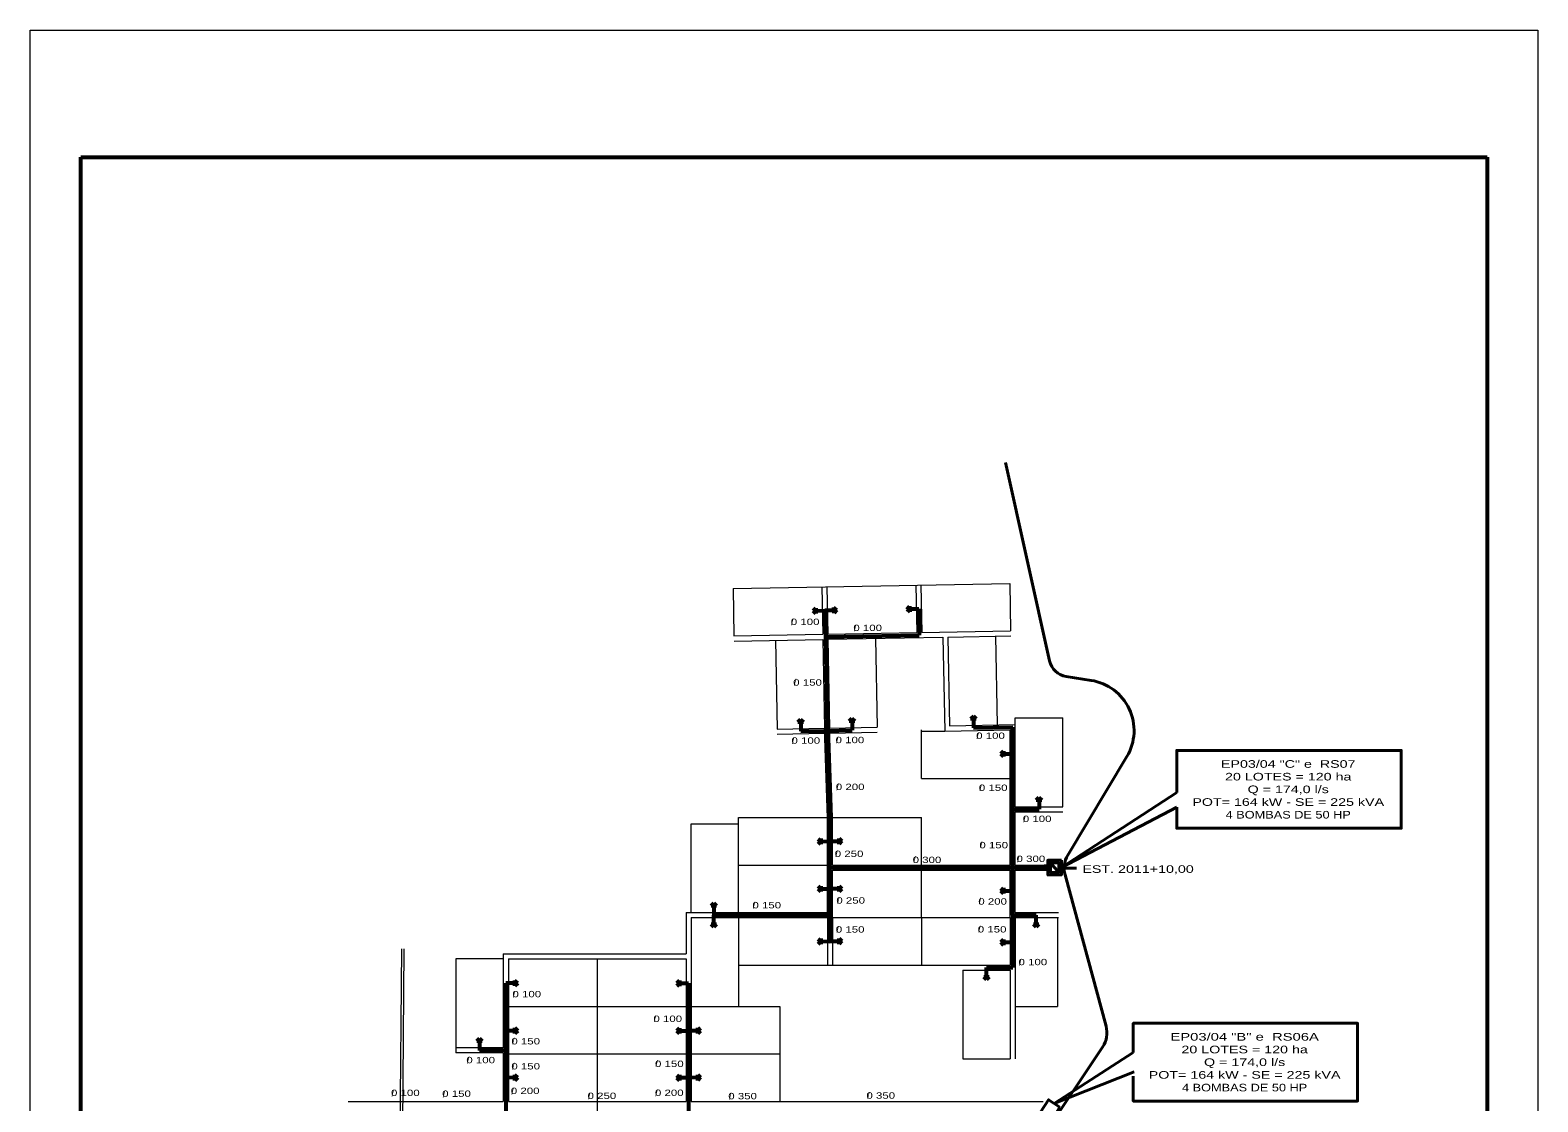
# Model space of a CAD drawing. Extents: x 312964 to 351929, y 9004151 to 9034973.
# Drawn here: x 326200 to 332140, y 9017535 to 9021758 of the extents above; entities that cross this region are included whole.
import ezdxf
from ezdxf.enums import TextEntityAlignment as Align

# ---------------------------------------------------------------- set-up
doc = ezdxf.new("R2010")
doc.units = 0
doc.header["$LTSCALE"] = 10
for name, color, linetype, lineweight in [('1', 7, 'Continuous', 13), ('2', 7, 'Continuous', 53), ('6', 7, 'Continuous', 13)]:
    doc.layers.add(name, color=color, linetype=linetype, lineweight=lineweight)

msp = doc.modelspace()

# ---------------------------------------------------------------- linework, layer by layer
at = {"layer": '1'}
for p, q in [((326200.21, 9017557.86), (326200.21, 9021757.86)), ((328969.59, 9019557.81), (328973.09, 9019370.84)), ((329319.53, 9019564.35), (329323.03, 9019377.38)), ((329339.53, 9019564.73), (329343.02, 9019377.76)), ((329689.47, 9019571.27), (329692.96, 9019384.3)), ((329709.46, 9019571.64), (329712.96, 9019384.67)), ((328973.09, 9019370.84), (329323.03, 9019377.38)), ((328973.46, 9019350.85), (329323.4, 9019357.39)), ((329323.4, 9019357.39), (329329.94, 9019007.31)), ((329343.02, 9019377.76), (329692.96, 9019384.3)), ((329343.4, 9019357.76), (329796.32, 9019366.23)), ((329343.4, 9019357.76), (329349.94, 9019007.82)), ((329530.36, 9019361.26), (329536.9, 9019011.32)), ((329712.96, 9019384.67), (330062.9, 9019391.21)), ((329816.31, 9019366.6), (330063.27, 9019371.22)), ((329816.31, 9019366.6), (329822.85, 9019016.66)), ((330003.28, 9019370.1), (330009.82, 9019020.16)), ((329136.43, 9019353.89), (329142.97, 9019003.95)), ((329142.97, 9019003.95), (329329.94, 9019007.45)), ((329341.4, 9018654.85), (329329.94, 9019007.31)), ((329349.94, 9019007.82), (329536.9, 9019011.32)), ((329361.4, 9018655.18), (329349.94, 9019007.82)), ((329711.4, 9018809.29), (329711.4, 9019001.12)), ((329822.85, 9019016.66), (330081.4, 9019021.49)), ((330061.4, 9018468.18), (330061.4, 9019001.12)), ((330081.4, 9019048.18), (330268.4, 9019048.18)), ((330081.4, 9018698.18), (330081.4, 9019048.18)), ((330268.4, 9018698.18), (330268.4, 9019048.18)), ((329143.35, 9018983.96), (329330.31, 9018987.45)), ((329350.31, 9018987.83), (329537.28, 9018991.32)), ((329711.4, 9018996.29), (329803.23, 9018996.29)), ((329711.4, 9018809.29), (330061.4, 9018809.29)), ((328991.4, 9018281.18), (328991.4, 9018655.18)), ((328991.4, 9018655.18), (329341.4, 9018655.18)), ((329341.4, 9018281.18), (329341.4, 9018654.85)), ((329361.4, 9018655.18), (329711.4, 9018655.18)), ((329361.4, 9018468.18), (329361.4, 9018655.18)), ((329711.4, 9018468.18), (329711.4, 9018655.18)), ((330081.4, 9018698.18), (330268.4, 9018698.18)), ((330081.4, 9018678.18), (330268.4, 9018678.18)), ((330081.4, 9018468.18), (330081.4, 9018678.18)), ((328804.4, 9018281.18), (328804.4, 9018631.18)), ((328804.4, 9018631.18), (328991.4, 9018631.18)), ((328991.4, 9018468.18), (329341.4, 9018468.18)), ((329361.4, 9018468.18), (330061.4, 9018468.18)), ((330081.4, 9018468.18), (330194.61, 9018468.18)), ((329361.4, 9018448.18), (330061.4, 9018448.18)), ((329361.4, 9018261.18), (329361.4, 9018448.18)), ((329711.4, 9018261.18), (329711.4, 9018448.18)), ((330061.4, 9018261.18), (330061.4, 9018448.18)), ((330081.4, 9018448.18), (330194.66, 9018448.18)), ((330081.4, 9018281.18), (330081.4, 9018448.18)), ((328784.4, 9018281.18), (328784.4, 9018118.18)), ((328784.4, 9018281.18), (329341.4, 9018281.18)), ((328804.4, 9018261.18), (329341.4, 9018261.18)), ((328804.4, 9018261.18), (328804.4, 9017537.18)), ((328991.4, 9018261.18), (328991.4, 9017911.18)), ((329341.4, 9018261.18), (329341.4, 9018074.18)), ((329361.4, 9018261.18), (329361.4, 9018074.18)), ((329361.4, 9018261.18), (330061.4, 9018261.18)), ((329711.4, 9018261.18), (329711.4, 9018074.18)), ((330061.4, 9018261.18), (330061.4, 9018074.18)), ((330081.4, 9018281.18), (330251.39, 9018281.18)), ((330081.4, 9018261.18), (330081.4, 9017704.18)), ((330081.4, 9018261.18), (330251.44, 9018261.18)), ((330248.4, 9018261.18), (330248.4, 9017911.18)), ((328064.4, 9018118.18), (328784.4, 9018118.18)), ((328064.4, 9018118.18), (328064.4, 9017748.18)), ((327877.4, 9018098.18), (327877.4, 9017728.18)), ((328064.4, 9018098.18), (327877.4, 9018098.18)), ((328084.4, 9018098.18), (328784.4, 9018098.18)), ((328084.4, 9018098.18), (328084.4, 9017537.18)), ((328434.4, 9018098.18), (328434.4, 9016208.18)), ((328784.4, 9018098.18), (328784.4, 9017537.18)), ((328991.4, 9018074.18), (330061.4, 9018074.18)), ((329874.4, 9018054.18), (330061.4, 9018054.18)), ((329874.4, 9018054.18), (329874.4, 9017704.18)), ((330061.4, 9018054.18), (330061.4, 9017704.18)), ((328084.4, 9017911.18), (329154.4, 9017911.18)), ((328804.4, 9017911.18), (329154.4, 9017911.18)), ((329154.4, 9017911.18), (329154.4, 9017537.18)), ((330081.4, 9017911.18), (330248.4, 9017911.18)), ((328064.4, 9017748.18), (327877.4, 9017748.18)), ((328064.4, 9017728.18), (327877.4, 9017728.18)), ((328064.4, 9017728.18), (328064.4, 9017537.18)), ((328084.4, 9017724.18), (328784.4, 9017724.18)), ((328804.4, 9017724.18), (329154.4, 9017724.18)), ((329874.4, 9017704.18), (330061.4, 9017704.18)), ((327453.4, 9017537.18), (328064.4, 9017537.18)), ((328084.4, 9017537.18), (328784.4, 9017537.18))]:
    msp.add_line(p, q, dxfattribs=at)
at = {"layer": '1', "lineweight": 53}
for p, q in [((326400.21, 9013557.86), (326400.21, 9021257.86)), ((326400.21, 9021257.86), (331940.21, 9021257.86)), ((331940.21, 9021257.86), (331940.21, 9013557.86))]:
    msp.add_line(p, q, dxfattribs=at)
at = {"layer": '1', "lineweight": 40}
for p, q in [((330216.08, 9019272.99), (330042.9, 9020054.18)), ((330380.24, 9019195.92), (330281.85, 9019211.26)), ((330288.23, 9018506.66), (330521.02, 9018895.59)), ((330209.65, 9018450.72), (330194.61, 9018465.68)), ((330209.61, 9018465.72), (330194.65, 9018450.68)), ((330219.58, 9018477.4), (330253.07, 9018439.16)), ((330439.01, 9017833.07), (330277.52, 9018429.15)), ((330190.37, 9017399.2), (330425.64, 9017751.37))]:
    msp.add_line(p, q, dxfattribs=at)
at = {"layer": '1'}
for points in [[(326200.21, 9021757.86), (332140.21, 9021757.86), (332140.21, 9017557.86)], [(328969.59, 9019557.81), (330059.4, 9019578.18), (330062.9, 9019391.21)], [(329796.32, 9019366.23), (329803.23, 9018996.29), (330061.4, 9019001.12)], [(332140.21, 9017557.86), (332140.21, 9013357.86), (326200.21, 9013357.86), (326200.21, 9017557.86)], [(328804.4, 9017537.18), (329154.4, 9017537.18), (330190.66, 9017537.18)]]:
    msp.add_lwpolyline(points, dxfattribs=at)
at = {"layer": '1', "lineweight": 40}
for points in [[(330194.61, 9018465.68), (330194.65, 9018450.68), (330209.65, 9018450.72), (330209.61, 9018465.72)], [(330262.95, 9018487.51), (330263.09, 9018429.19), (330209.7, 9018429.06), (330209.56, 9018487.38)], [(330252.97, 9018477.49), (330253.07, 9018439.16), (330219.68, 9018439.08), (330219.58, 9018477.4)], [(330219.58, 9018477.4), (330252.97, 9018477.49), (330253.07, 9018439.16)], [(330257.28, 9017514.07), (330225.3, 9017465.29), (330180.65, 9017494.57), (330212.63, 9017543.34)]]:
    msp.add_lwpolyline(points, close=True, dxfattribs=at)
for centre, radius, start, end in [((330294.19, 9019290.31), 80, 192.49974, 261.1331), ((330349.41, 9018998.31), 200, 329.09823, 81.13306), ((330374.04, 9018455.3), 100, 149.09824, 195.159), ((330342.49, 9017806.92), 100, 326.25468, 15.15895)]:
    msp.add_arc(centre, radius, start, end, dxfattribs=at)
at = {"layer": '2'}
for p, q in [((329284.66, 9019469.93), (329295.24, 9019480.91)), ((329295.24, 9019480.91), (329295.64, 9019459.35)), ((329367.31, 9019461.2), (329366.91, 9019482.76)), ((329377.89, 9019472.18), (329366.91, 9019482.76)), ((329654.6, 9019476.84), (329665.17, 9019487.82)), ((329654.6, 9019476.84), (329665.57, 9019466.27)), ((329665.17, 9019487.82), (329665.57, 9019466.27)), ((329665.37, 9019477.3), (329701.21, 9019477.97)), ((329701.21, 9019477.97), (329703.15, 9019374.49)), ((329284.66, 9019469.93), (329295.64, 9019459.35)), ((329295.43, 9019470.39), (329331.28, 9019471.05)), ((329367.12, 9019471.72), (329331.28, 9019471.05)), ((329331.28, 9019471.06), (329333.21, 9019367.57)), ((329377.89, 9019472.18), (329367.31, 9019461.2)), ((329333.21, 9019367.57), (329703.15, 9019374.49)), ((329333.21, 9019367.57), (329339.94, 9019007.64)), ((329235.65, 9019042.32), (329225.08, 9019031.34)), ((329246.63, 9019031.74), (329225.08, 9019031.34)), ((329235.65, 9019042.32), (329246.63, 9019031.74)), ((329236.11, 9019031.55), (329236.78, 9018995.71)), ((329335.33, 9018997.55), (329438.81, 9018999.48)), ((329351.41, 9018654.86), (329339.94, 9019007.5)), ((329437.69, 9019046.1), (329427.11, 9019035.12)), ((329448.66, 9019035.52), (329427.11, 9019035.12)), ((329437.69, 9019046.1), (329448.66, 9019035.52)), ((329438.15, 9019035.32), (329438.81, 9018999.48)), ((329916.42, 9019055.04), (329905.61, 9019044.3)), ((329927.17, 9019044.22), (329905.61, 9019044.3)), ((329916.42, 9019055.04), (329927.17, 9019044.22)), ((329916.64, 9019044.26), (329916.52, 9019008.41)), ((329916.52, 9019008.41), (330071.4, 9019011.31)), ((330071.4, 9018271.18), (330071.4, 9019011.31)), ((329236.78, 9018995.71), (329340.26, 9018997.64)), ((330024.77, 9018906.39), (330035.59, 9018917.14)), ((330024.77, 9018906.39), (330035.52, 9018895.58)), ((330035.59, 9018917.14), (330035.52, 9018895.58)), ((330035.55, 9018906.62), (330071.4, 9018906.5)), ((330174.8, 9018734.81), (330163.98, 9018724.07)), ((330185.54, 9018723.99), (330163.98, 9018724.07)), ((330174.8, 9018734.81), (330185.54, 9018723.99)), ((330175.02, 9018724.03), (330174.9, 9018688.18)), ((330071.4, 9018688.18), (330174.9, 9018688.18)), ((329304.77, 9018561.58), (329315.59, 9018572.32)), ((329304.77, 9018561.58), (329315.52, 9018550.76)), ((329315.59, 9018572.32), (329315.52, 9018550.76)), ((329315.55, 9018561.8), (329351.4, 9018561.68)), ((329387.25, 9018561.56), (329351.4, 9018561.68)), ((329387.21, 9018551.04), (329387.29, 9018572.6)), ((329398.03, 9018561.78), (329387.21, 9018551.04)), ((329398.03, 9018561.78), (329387.29, 9018572.6)), ((329351.4, 9018458.18), (330194.63, 9018458.18)), ((329304.77, 9018374.58), (329315.59, 9018385.32)), ((329304.77, 9018374.58), (329315.52, 9018363.76)), ((329315.59, 9018385.32), (329315.52, 9018363.76)), ((329315.55, 9018374.8), (329351.4, 9018374.68)), ((329387.25, 9018374.56), (329351.4, 9018374.68)), ((329387.21, 9018364.04), (329387.29, 9018385.6)), ((329398.03, 9018374.78), (329387.21, 9018364.04)), ((329398.03, 9018374.78), (329387.29, 9018385.6)), ((330024.77, 9018367.16), (330035.59, 9018377.9)), ((330024.77, 9018367.16), (330035.52, 9018356.35)), ((330035.59, 9018377.9), (330035.52, 9018356.35)), ((330035.55, 9018367.38), (330071.4, 9018367.26)), ((328893.88, 9018317.81), (328883.06, 9018307.07)), ((328904.62, 9018306.99), (328883.06, 9018307.07)), ((328893.88, 9018317.81), (328904.62, 9018306.99)), ((328894.1, 9018307.03), (328893.98, 9018271.18)), ((328883.34, 9018235.37), (328904.9, 9018235.3)), ((328894.08, 9018224.55), (328883.34, 9018235.37)), ((328893.86, 9018235.33), (328893.98, 9018271.18)), ((328894.08, 9018224.55), (328904.9, 9018235.3)), ((329351.4, 9018271.18), (329351.4, 9018167.68)), ((330071.4, 9018271.18), (330071.4, 9018064.18)), ((330071.4, 9018271.18), (330163.57, 9018271.18)), ((330152.93, 9018235.37), (330174.49, 9018235.3)), ((330163.68, 9018224.55), (330152.93, 9018235.37)), ((330163.45, 9018235.33), (330163.57, 9018271.18)), ((330163.68, 9018224.55), (330174.49, 9018235.3)), ((329304.77, 9018167.58), (329315.59, 9018178.32)), ((329304.77, 9018167.58), (329315.52, 9018156.76)), ((329315.59, 9018178.32), (329315.52, 9018156.76)), ((329315.55, 9018167.8), (329351.4, 9018167.68)), ((329387.25, 9018167.56), (329351.4, 9018167.68)), ((329387.21, 9018157.04), (329387.29, 9018178.6)), ((329398.03, 9018167.78), (329387.21, 9018157.04)), ((329398.03, 9018167.78), (329387.29, 9018178.6)), ((330024.77, 9018164.03), (330035.59, 9018174.77)), ((330035.59, 9018174.77), (330035.52, 9018153.21)), ((330024.77, 9018164.03), (330035.52, 9018153.21)), ((330035.55, 9018164.25), (330071.4, 9018164.13)), ((329967.78, 9018028.33), (329967.9, 9018064.18)), ((329967.9, 9018064.18), (330071.4, 9018064.18)), ((328110.25, 9018002.9), (328074.4, 9018003.02)), ((328110.21, 9017992.38), (328110.29, 9018013.94)), ((328121.03, 9018003.12), (328110.21, 9017992.38)), ((328121.03, 9018003.12), (328110.29, 9018013.94)), ((328747.77, 9018002.55), (328758.59, 9018013.29)), ((328747.77, 9018002.55), (328758.52, 9017991.73)), ((328758.59, 9018013.29), (328758.52, 9017991.73)), ((328758.55, 9018002.77), (328794.4, 9018002.65)), ((329957.26, 9018028.37), (329978.82, 9018028.3)), ((329968, 9018017.55), (329957.26, 9018028.37)), ((329968, 9018017.55), (329978.82, 9018028.3)), ((328110.25, 9017815.3), (328074.4, 9017815.42)), ((328110.21, 9017804.78), (328110.29, 9017826.34)), ((328121.03, 9017815.52), (328110.21, 9017804.78)), ((328121.03, 9017815.52), (328110.29, 9017826.34)), ((328748.33, 9017815.46), (328759.14, 9017826.21)), ((328748.33, 9017815.46), (328759.07, 9017804.65)), ((328759.14, 9017826.21), (328759.07, 9017804.65)), ((328759.11, 9017815.68), (328794.96, 9017815.56)), ((328830.81, 9017815.44), (328794.96, 9017815.56)), ((328830.77, 9017804.92), (328830.84, 9017826.48)), ((328841.59, 9017815.67), (328830.77, 9017804.92)), ((328841.59, 9017815.67), (328830.84, 9017826.48)), ((327970.8, 9017784.81), (327959.98, 9017774.07)), ((327981.54, 9017773.99), (327959.98, 9017774.07)), ((327970.8, 9017784.81), (327981.54, 9017773.99)), ((327971.02, 9017774.03), (327970.9, 9017738.18)), ((328074.4, 9017738.18), (327970.9, 9017738.18)), ((328110.21, 9017620.04), (328110.29, 9017641.6)), ((328121.03, 9017630.78), (328110.29, 9017641.6)), ((328747.77, 9017630.58), (328758.59, 9017641.32)), ((328758.59, 9017641.32), (328758.52, 9017619.76)), ((328830.21, 9017620.04), (328830.29, 9017641.6)), ((328841.03, 9017630.78), (328830.29, 9017641.6)), ((328110.25, 9017630.56), (328074.4, 9017630.68)), ((328121.03, 9017630.78), (328110.21, 9017620.04)), ((328747.77, 9017630.58), (328758.52, 9017619.76)), ((328758.55, 9017630.8), (328794.4, 9017630.68)), ((328830.25, 9017630.56), (328794.4, 9017630.68)), ((328841.03, 9017630.78), (328830.21, 9017620.04))]:
    msp.add_line(p, q, dxfattribs=at)
at = {"layer": '2', "lineweight": 40}
for p, q in [((330274.04, 9018455.79), (330321.96, 9018455.56)), ((330545.86, 9017730.28), (330234.96, 9017528.71)), ((330550.35, 9017653.91), (330234.96, 9017528.71))]:
    msp.add_line(p, q, dxfattribs=at)
for points in [[(330717.56, 9018754.01), (330717.56, 9018919.89), (330895.05, 9018919.89)], [(330895.05, 9018919.89), (331601.79, 9018919.89), (331601.79, 9018613.07), (330717.56, 9018613.07), (330717.56, 9018695.89)], [(330895.05, 9018919.89), (331601.79, 9018919.89), (331601.79, 9018613.07), (330717.56, 9018613.07), (330717.56, 9018695.89)], [(330717.56, 9018754.01), (330263.02, 9018458.35), (330717.56, 9018695.89)], [(330723.36, 9017844.85), (331430.09, 9017844.85), (331430.09, 9017538.02), (330545.86, 9017538.02), (330545.86, 9017635.94)], [(330545.86, 9017730.28), (330545.86, 9017844.85), (330723.36, 9017844.85)]]:
    msp.add_lwpolyline(points, dxfattribs=at)
at = {"layer": '2'}
for points in [[(328893.98, 9018271.18), (329351.4, 9018271.18), (329351.4, 9018655.18)], [(328074.4, 9018003.02), (328074.4, 9017527.18), (328074.4, 9017255.42)], [(328794.4, 9018002.65), (328794.4, 9017527.18), (328794.4, 9017256.68)]]:
    msp.add_lwpolyline(points, dxfattribs=at)
at = {"layer": '6'}
msp.add_line((327654.4, 9016921.26), (327664.4, 9018138.26), dxfattribs=at)
msp.add_lwpolyline([(327645.24, 9016081.85), (327644.4, 9016210.18), (327664.4, 9016921.18), (327674.4, 9018138.18)], dxfattribs=at)

# ---------------------------------------------------------------- texts
at = {"layer": '2'}
for p in [(329202.73, 9019413.57), (329450.22, 9019389.66), (329213.83, 9019175.72), (329205.9, 9018945.63), (329379.83, 9018947.87), (329933.57, 9018964.9), (329381.41, 9018763.51), (329945.2, 9018760.34), (330117.88, 9018636.87), (329377.53, 9018500.53), (329947.31, 9018535.27), (329685.01, 9018477.95), (330093.34, 9018479.34), (329052.11, 9018297.16), (329384.68, 9018316.18), (329942.64, 9018314.11), (329381.51, 9018202.06), (329940.52, 9018203.16), (330101, 9018072.14), (328106.26, 9017945.77), (328662, 9017849.71), (328104.18, 9017762.43), (327925.76, 9017686.36), (328668.64, 9017673.66), (328104.18, 9017663.11), (327628.82, 9017555.85), (327830.5, 9017552.48), (328100.93, 9017563.71), (328668.08, 9017557.99), (329503.04, 9017547.98), (328402.79, 9017545.73), (328958.25, 9017544.6)]:
    msp.add_text('/', height=25, dxfattribs=at).set_placement(p, align=Align.CENTER)
for s, height, width, p in [('0 100', 25, 1.35, (329253.43, 9019414.23)), ('0 100', 25, 1.35, (329499.92, 9019390.32)), ('0 150', 25, 1.35, (329263.01, 9019175.26)), ('0 100', 25, 1.35, (329256.07, 9018946.29)), ('0 100', 25, 1.35, (329430, 9018948.54)), ('0 100', 25, 1.35, (329983.81, 9018965.47)), ('EP03/04 "C" e  RS07', 30, 1.4, (331156.74, 9018851.55)), ('20 LOTES = 120 ha', 30, 1.4, (331156.74, 9018801.55)), ('0 200', 25, 1.35, (329430.91, 9018763.74)), ('0 150', 25, 1.35, (329994.37, 9018760.48)), ('Q = 174,0 l/s', 30, 1.4, (331156.74, 9018751.55)), ('POT= 164 kW - SE = 225 kVA', 30, 1.4, (331156.74, 9018701.55)), ('0 100', 25, 1.35, (330167.52, 9018637.91)), ('4 BOMBAS DE 50 HP', 30, 1.25, (331156.74, 9018651.55)), ('0 250', 25, 1.35, (329426.63, 9018500.27)), ('0 150', 25, 1.35, (329996.48, 9018534.36)), ('0 300', 25, 1.35, (329733.57, 9018476.24)), ('0 300', 25, 1.35, (330142.96, 9018480.46)), ('EST. 2011+10,00', 30, 1.4, (330565.2, 9018437.48)), ('0 150', 25, 1.35, (329102.24, 9018297.57)), ('0 250', 25, 1.35, (329432.97, 9018316.42)), ('0 200', 25, 1.35, (329992.26, 9018312.47)), ('0 150', 25, 1.35, (329430.85, 9018202.3)), ('0 150', 25, 1.35, (329990.15, 9018202.58)), ('0 100', 25, 1.35, (330150.62, 9018073.67)), ('0 100', 25, 1.35, (328156.83, 9017947.42)), ('0 100', 25, 1.35, (328712.17, 9017850.21)), ('0 150', 25, 1.35, (328152.6, 9017761.45)), ('EP03/04 "B" e  RS06A', 30, 1.45, (330985.04, 9017776.51)), ('20 LOTES = 120 ha', 30, 1.4, (330985.04, 9017726.51)), ('0 100', 25, 1.35, (327975.23, 9017687.49)), ('0 150', 25, 1.35, (328718.5, 9017672.7)), ('Q = 174,0 l/s', 30, 1.4, (330985.04, 9017676.51)), ('0 150', 25, 1.35, (328152.57, 9017662.94)), ('POT= 164 kW - SE = 225 kVA', 30, 1.4, (330985.04, 9017626.51)), ('0 100', 25, 1.35, (327678.4, 9017558.36)), ('0 150', 25, 1.35, (327880.08, 9017554.99)), ('0 200', 25, 1.35, (328150.51, 9017566.22)), ('0 200', 25, 1.35, (328718.31, 9017558.62)), ('4 BOMBAS DE 50 HP', 30, 1.25, (330985.04, 9017576.51)), ('0 250', 25, 1.35, (328452.82, 9017546.61)), ('0 350', 25, 1.35, (329007.15, 9017545.48)), ('0 350', 25, 1.35, (329551.39, 9017547.76))]:
    msp.add_text(s, height=height, dxfattribs=dict(at, width=width)).set_placement(p, align=Align.CENTER)

doc.saveas('drawing.dxf')
